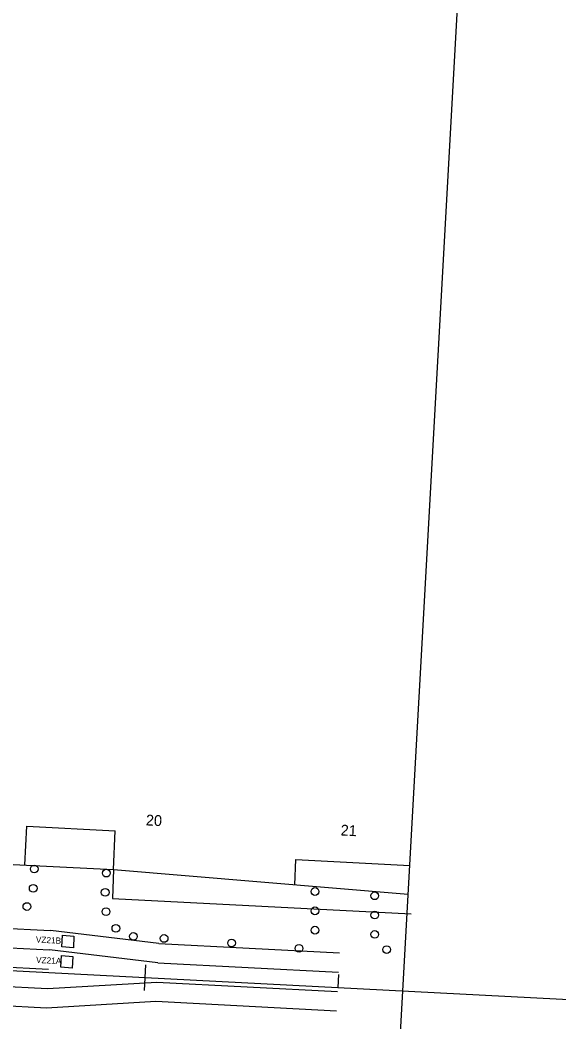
# Model space of a CAD drawing. Extents: x 679444 to 687671, y 733868 to 736107.
# Drawn here: x 681215 to 681494, y 735101 to 735619 of the extents above; entities that cross this region are included whole.
import ezdxf

# ---------------------------------------------------------------- set-up
doc = ezdxf.new("R2010")
doc.units = 0
for name, color, linetype in [('$', 7, 'Continuous'), ('border All Plan 20-40_Border 1 - Level 1', 7, 'Continuous'), ('MOT Stage 1', 7, 'Continuous'), ('MOT Stage 1 Lanes', 7, 'Continuous'), ('R_Horz Alg Station', 7, 'Continuous'), ('RW-EX', 7, 'Continuous'), ('RW-PR', 7, 'Continuous'), ('Video-Zones-pr', 7, 'Continuous')]:
    doc.layers.add(name, color=color, linetype=linetype)

# ---------------------------------------------------------------- blocks, each defined once
blk = doc.blocks.new('BAREL_1508')
at = {"layer": 'MOT Stage 1'}
blk.add_circle((0, 0.01), 2.88, dxfattribs=at)
blk = doc.blocks.new('BAREL_1509')
at = {"layer": 'MOT Stage 1'}
blk.add_circle((0, 0.01), 2.88, dxfattribs=at)
blk = doc.blocks.new('BAREL_1510')
at = {"layer": 'MOT Stage 1'}
blk.add_circle((0, 0.01), 2.88, dxfattribs=at)
blk = doc.blocks.new('BAREL_1511')
at = {"layer": 'MOT Stage 1'}
blk.add_circle((0, 0.01), 2.88, dxfattribs=at)
blk = doc.blocks.new('BAREL_1512')
at = {"layer": 'MOT Stage 1'}
blk.add_circle((0, 0.01), 2.88, dxfattribs=at)
blk = doc.blocks.new('BAREL_1513')
at = {"layer": 'MOT Stage 1'}
blk.add_circle((0, 0.01), 2.88, dxfattribs=at)
blk = doc.blocks.new('BAREL_1527')
at = {"layer": 'MOT Stage 1'}
blk.add_circle((0, 0.01), 2.88, dxfattribs=at)
blk = doc.blocks.new('BAREL_1528')
at = {"layer": 'MOT Stage 1'}
blk.add_circle((0, 0.01), 2.88, dxfattribs=at)
blk = doc.blocks.new('BAREL_1529')
at = {"layer": 'MOT Stage 1'}
blk.add_circle((0, 0.01), 2.88, dxfattribs=at)
blk = doc.blocks.new('BAREL_1530')
at = {"layer": 'MOT Stage 1'}
blk.add_circle((0, 0.01), 2.88, dxfattribs=at)
blk = doc.blocks.new('BAREL_1531')
at = {"layer": 'MOT Stage 1'}
blk.add_circle((0, 0.01), 2.88, dxfattribs=at)
blk = doc.blocks.new('BAREL_1535')
at = {"layer": 'MOT Stage 1'}
blk.add_circle((0, 0.01), 2.88, dxfattribs=at)
blk = doc.blocks.new('BAREL_1536')
at = {"layer": 'MOT Stage 1'}
blk.add_circle((0, 0.01), 2.88, dxfattribs=at)
blk = doc.blocks.new('BAREL_1537')
at = {"layer": 'MOT Stage 1'}
blk.add_circle((0, 0.01), 2.88, dxfattribs=at)
blk = doc.blocks.new('BAREL_1538')
at = {"layer": 'MOT Stage 1'}
blk.add_circle((0, 0.01), 2.88, dxfattribs=at)
blk = doc.blocks.new('BAREL_1539')
at = {"layer": 'MOT Stage 1'}
blk.add_circle((0, 0.01), 2.88, dxfattribs=at)
blk = doc.blocks.new('BAREL_1540')
at = {"layer": 'MOT Stage 1'}
blk.add_circle((0, 0.01), 2.88, dxfattribs=at)
blk = doc.blocks.new('BAREL_1595')
at = {"layer": 'MOT Stage 1'}
blk.add_circle((0, 0.01), 2.88, dxfattribs=at)

msp = doc.modelspace()

# ---------------------------------------------------------------- linework, layer by layer
at = {"layer": 'border All Plan 20-40_Border 1 - Level 1'}
msp.add_line((681384.1, 734599.57), (681440.93, 735625.3), dxfattribs=at)
at = {"layer": 'MOT Stage 1 Lanes'}
for p, q in [((681043.86, 735157.43), (681230.33, 735147.83)), ((681286.32, 735141.17), (681230.33, 735147.83)), ((681286.32, 735141.17), (681379.94, 735136.33)), ((681042.83, 735137.46), (681229.3, 735127.86)), ((681202.27, 735139.26), (681229.82, 735137.84)), ((681285.8, 735131.19), (681229.82, 735137.84)), ((681285.8, 735131.19), (681379.43, 735126.35)), ((681228.79, 735117.87), (681285.29, 735121.2)), ((681285.29, 735121.2), (681378.91, 735116.36)), ((681041.8, 735117.48), (681228.28, 735107.88)), ((681228.28, 735107.88), (681284.77, 735111.21)), ((681284.77, 735111.21), (681378.4, 735106.37))]:
    msp.add_line(p, q, dxfattribs=at)
msp.add_lwpolyline([(681042.86, 735157.48), (681041.31, 735127.52), (681228.79, 735117.87)], dxfattribs=at)
at = {"layer": 'R_Horz Alg Station'}
msp.add_line((680979.55, 735139), (682304.99, 735070.5), dxfattribs=at)
for points in [[(681279.49, 735130.18), (681278.8, 735116.86)], [(681379.36, 735125.02), (681379.02, 735118.36)]]:
    msp.add_lwpolyline(points, dxfattribs=at)
at = {"layer": 'RW-EX'}
msp.add_lwpolyline([(681053.04, 735199.88), (681077.83, 735182.39), (681128.41, 735179.07), (681183.11, 735183.4), (681262.95, 735179.36), (681262.33, 735164.44), (681417.02, 735156.45)], dxfattribs=at)
at = {"layer": 'RW-PR'}
for p, q in [((681217.07, 735181.8), (681218.11, 735201.77)), ((681218.11, 735201.77), (681263.79, 735199.41)), ((681262.96, 735179.43), (681263.79, 735199.41)), ((681356.73, 735171.54), (681357.4, 735184.56)), ((681357.4, 735184.56), (681416.35, 735181.51))]:
    msp.add_line(p, q, dxfattribs=at)
msp.add_lwpolyline([(681262.96, 735179.43), (681415.52, 735166.6)], dxfattribs=at)
at = {"layer": 'Video-Zones-pr'}
msp.add_lwpolyline([(681236.18, 735139.38), (681236.49, 735145.38), (681242.48, 735144.93), (681242.17, 735138.94), (681236.18, 735139.38)], dxfattribs=at)
msp.add_lwpolyline([(681235.95, 735134.84), (681241.93, 735134.39), (681241.62, 735128.4), (681235.64, 735128.84)], close=True, dxfattribs=at)

# ---------------------------------------------------------------- block references
at = {"layer": 'MOT Stage 1', "xscale": 0.6945420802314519, "yscale": 0.6945420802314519, "rotation": 87.04179557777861}
for name, p in [('BAREL_1527', (681221.92, 735179.69)), ('BAREL_1528', (681259.2, 735177.56)), ('BAREL_1539', (681221.37, 735169.7)), ('BAREL_1535', (681258.64, 735167.58)), ('BAREL_1508', (681367.24, 735168.03)), ('BAREL_1509', (681398.18, 735165.83)), ('BAREL_1540', (681218.09, 735160.26)), ('BAREL_1536', (681259.07, 735157.59)), ('BAREL_1510', (681367.24, 735158.03)), ('BAREL_1512', (681398.18, 735155.83)), ('BAREL_1537', (681264.17, 735148.98)), ('BAREL_1538', (681273.25, 735144.79)), ('BAREL_1529', (681289.15, 735143.75)), ('BAREL_1511', (681367.24, 735148.03)), ('BAREL_1513', (681398.18, 735145.83)), ('BAREL_1530', (681324.07, 735141.39)), ('BAREL_1531', (681358.97, 735138.63)), ('BAREL_1595', (681404.37, 735137.99))]:
    msp.add_blockref(name, p, dxfattribs=at)

# ---------------------------------------------------------------- texts
at = {"layer": '$'}
for s, height, rotation, p in [('20', 5.6, 357.0415, (681279.59, 735202.27)), ('21', 5.6, 357.0415, (681380.41, 735197.06)), ('VZ21B', 3.2, 357.065, (681222.68, 735141.64)), ('VZ21A', 3.2, 357.065, (681222.77, 735131.12))]:
    msp.add_text(s, height=height, rotation=rotation, dxfattribs=at).set_placement(p)

doc.saveas('drawing.dxf')
